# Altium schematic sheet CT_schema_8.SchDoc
size 405 x 220 mm
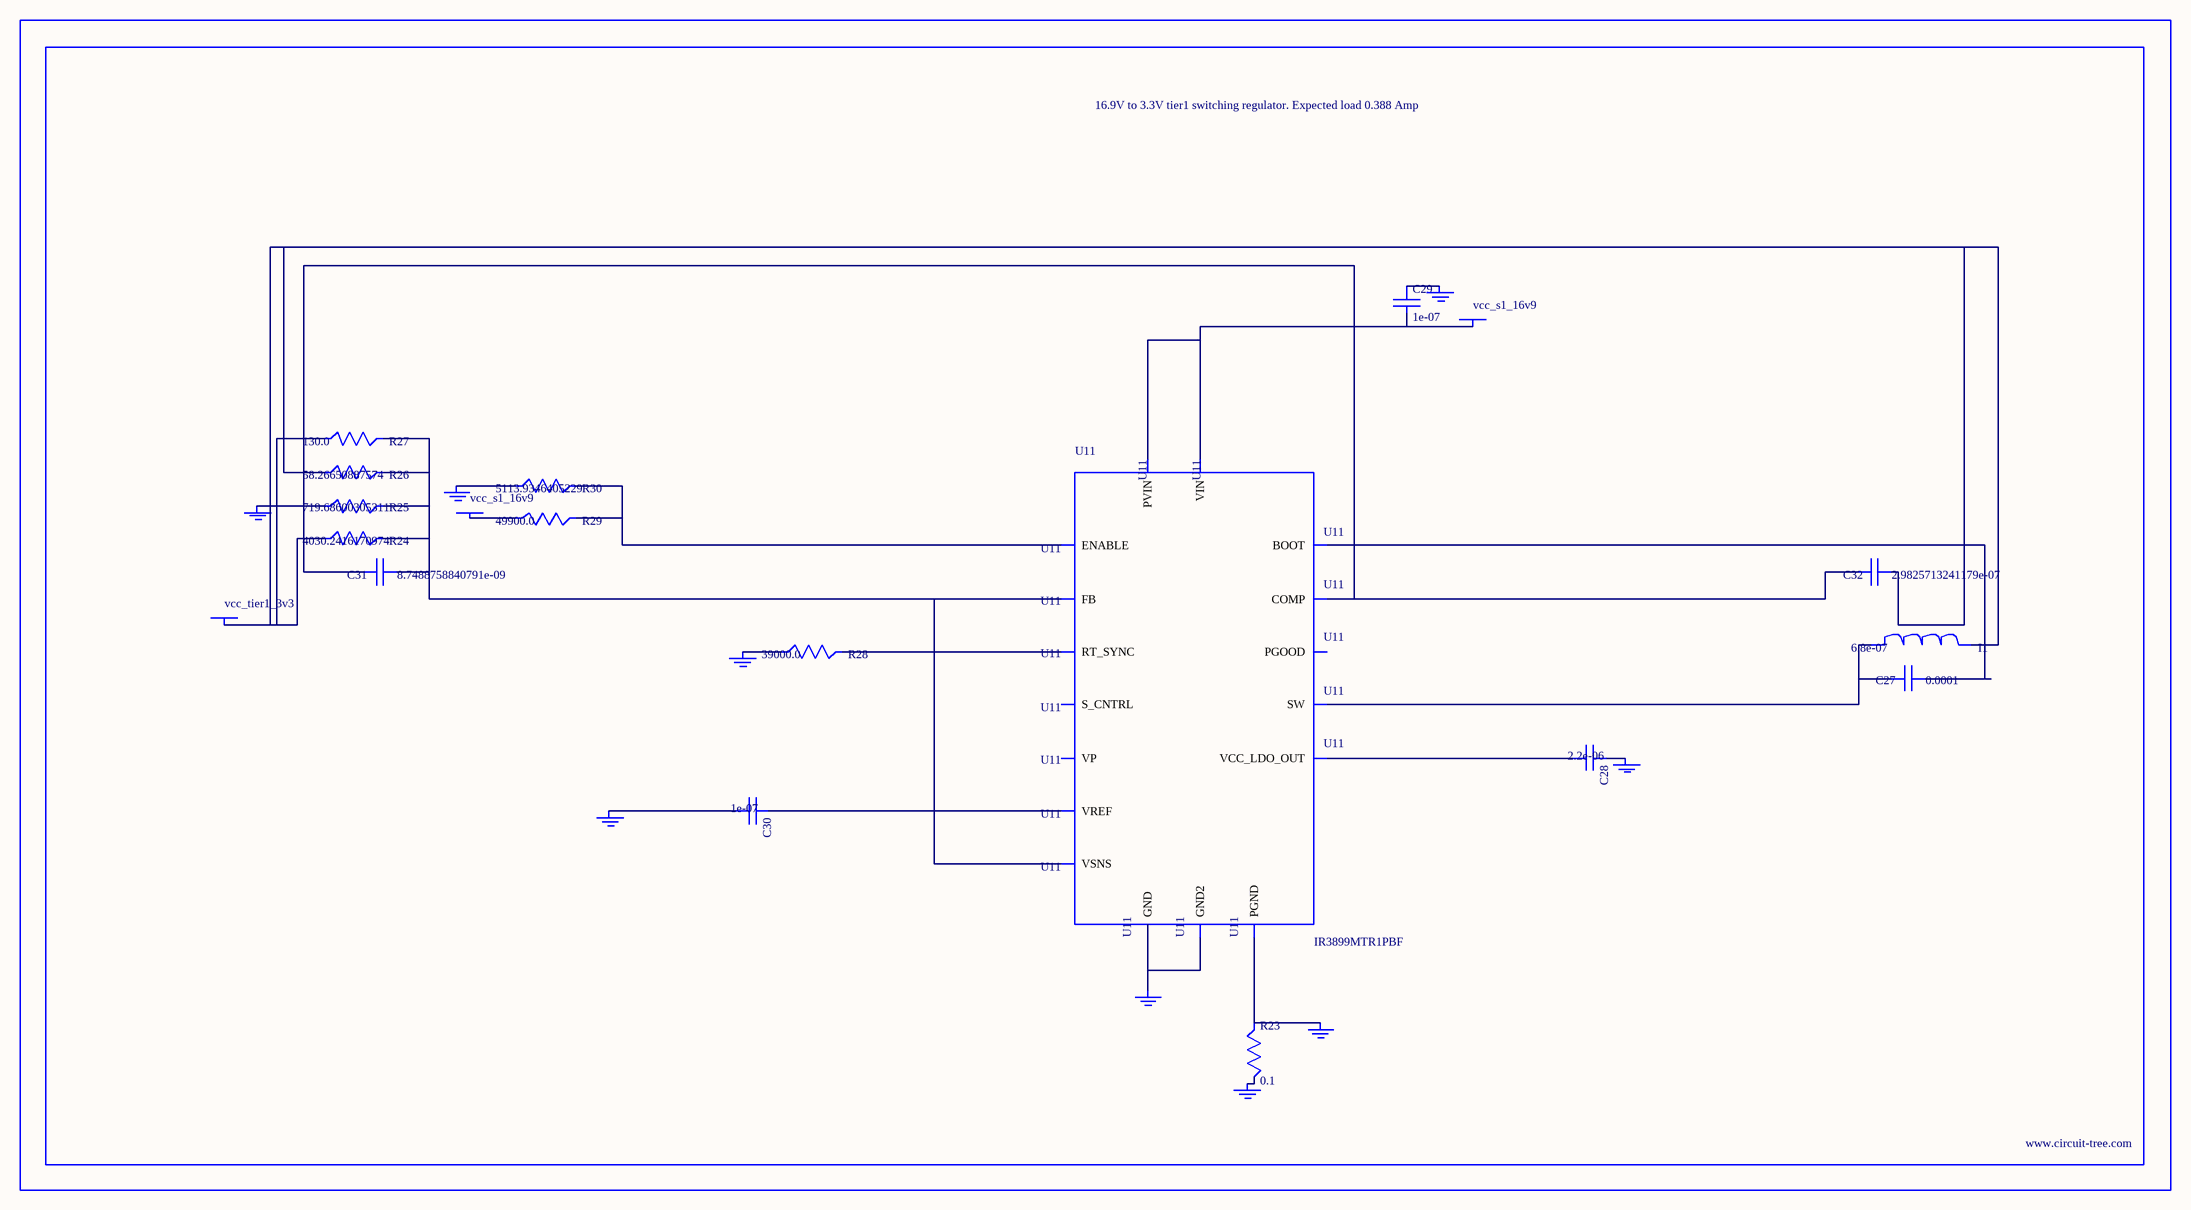
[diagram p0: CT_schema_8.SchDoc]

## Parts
BORDER7  (no value)
C27  0.0001  [C1210]
C28  2.2e-06  [C0603]
C29  1e-07  [C0402]
C30  1e-07  [C0402]
C31  8.7488758840791e-09  [R0603]
C32  2.9825713241179e-07  [R0603]
GND_INSTANCE_7_0  (no value)
GND_INSTANCE_7_1  (no value)
GND_INSTANCE_7_2  (no value)
GND_INSTANCE_7_3  (no value)
GND_INSTANCE_7_4  (no value)
GND_INSTANCE_7_5  (no value)
GND_INSTANCE_7_6  (no value)
GND_INSTANCE_7_7  (no value)
GND_INSTANCE_7_8  (no value)
I1  6.8e-07  [IND25X25CZ]
POWER_INSTANCE_7_0  vcc_s1_16v9
POWER_INSTANCE_7_1  vcc_s1_16v9
POWER_INSTANCE_7_2  vcc_tier1_3v3
R23  0.1  [R0603]
R24  4030.2416170974  [R0603]
R25  719.68600305311  [R0603]
R26  58.26650887574  [R0603]
R27  130.0  [R0603]
R28  39000.0  [R0603]
R29  49900.0  [R0603]
R30  5113.9346405229  [R0603]
U11  IR3899MTR1PBF  [IR3899MTR1PBF]

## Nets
NetC27_1: C27.1 U11.14(BOOT)
NetC27_2: C27.2 I1.1 U11.12(SW)
NetC28_1: C28.1 GND_INSTANCE_7_4.0(GND)
NetC28_2: C28.2 U11.10(VCC_LDO_OUT)
NetC29_1: C29.1 GND_INSTANCE_7_3.0(GND)
NetC29_2: C29.2 POWER_INSTANCE_7_0.0(PWR) U11.9(VIN) U11.13(PVIN)
NetC30_1: C30.1 U11.2(VREF)
NetC30_2: C30.2 GND_INSTANCE_7_1.0(GND)
NetC31_1: C31.1 R24.2 R25.2 R26.2 R27.2 U11.1(FB) U11.8(VSNS)
NetC31_2: C31.2 C32.2 U11.3(COMP)
NetC32_1: C32.1 I1.2 POWER_INSTANCE_7_2.0(PWR) R24.1 R26.1 R27.1
NetGND_INSTANCE_7_0_0: GND_INSTANCE_7_0.0(GND) R25.1
NetGND_INSTANCE_7_2_0: GND_INSTANCE_7_2.0(GND) R28.1
NetGND_INSTANCE_7_5_0: GND_INSTANCE_7_5.0(GND) R23.2
NetGND_INSTANCE_7_6_0: GND_INSTANCE_7_6.0(GND) R23.1 U11.11(PGND)
NetGND_INSTANCE_7_7_0: GND_INSTANCE_7_7.0(GND) R30.1
NetGND_INSTANCE_7_8_0: GND_INSTANCE_7_8.0(GND) U11.4(GND) U11.17(GND2)
NetPOWER_INSTANCE_7_1_0: POWER_INSTANCE_7_1.0(PWR) R29.1
NetR28_2: R28.2 U11.5(RT_SYNC)
NetR29_2: R29.2 R30.2 U11.15(ENABLE)

Not connected (* = marked no-connect by the designer): U11 6(S_CNTRL) 7(PGOOD) 16(VP)

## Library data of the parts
BORDER7 = BORDER_PAGE7
C27 = GRM32ER61A107ME20L
C28 = C0603C225K8RACTU
C29 C30 = C0402C104K3RACTU
C31 = C31
C32 = C32
GND_INSTANCE_7_0-GND_INSTANCE_7_8 = GND
I1 = IHLP2525CZERR68M01
POWER_INSTANCE_7_0-POWER_INSTANCE_7_2 = PWR
R23 = ERJ-3RSFR10V
R24 = R24
R25 = R25
R26 = R26
R27 = RC0603JR-07130RL
R28 = RC0603JR-0739KL
R29 = RC0603FR-0749K9
R30 = R30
